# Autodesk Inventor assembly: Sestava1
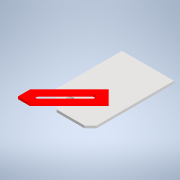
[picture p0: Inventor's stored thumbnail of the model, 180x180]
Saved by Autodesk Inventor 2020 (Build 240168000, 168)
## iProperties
Created: 2021-01
Part Number: Sestava1
Document SubType Name: Assembly
Designer: Pavel
Author: Pavel
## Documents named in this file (3)
- D:\Plocha\Zkouška\Sestava1.iam
- D:\Plocha\Zkouška\Deska.ipt
- D:\Plocha\Zkouška\Posuv.ipt
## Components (2 placed, 2 different names)
1. Deska:1 — Proti sobě:1, Úhel:1
2. Posuv:1 — Proti sobě:1, Úhel:1
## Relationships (2: Mate 1, Angle 1)
- Proti sobě:1 [Mate]: Deska:1 ↔ Posuv:1
- Úhel:1 [Angle]: Deska:1 ↔ Posuv:1
